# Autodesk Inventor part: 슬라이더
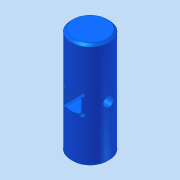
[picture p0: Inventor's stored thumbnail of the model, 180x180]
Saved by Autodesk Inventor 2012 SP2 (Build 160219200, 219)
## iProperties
Company: 한국ATC센터
Created: 2015-04
Part Number: 슬라이더
Document SubType Name: Modeling
Designer: KYOUNG IL JANG
Density: 7.85 g/cm^3
Material: 강
Author: KYOUNG IL JANG
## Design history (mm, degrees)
sketch "스케치1"
  geometry: C1 r 9 at (0, 0); 1 further point
  constraints: 1 centre point, 1 coincident
  dimensions: "d0" = 18 diameter of C1
extrude "돌출1" new body sketch "스케치1" stored distance "d1" = 50; taper "d2" = 0 deg
node "작업 평면1"
sketch "스케치3"
  geometry: L1 (4, 25)-(-4, 25); L2 (-4, 25)-(-4, -25); L3 (-4, -25)-(4, -25); L4 (4, -25)-(4, 25); 3 further points
  constraints: 8 end point, 2 midpoint, 2 parallel, 1 horizontal, 1 horizontal alignment, 1 perpendicular, 1 vertical alignment
  dimensions: "d5" = 8 distance of L1.start L1.end; "d6" = 50 distance of L1.end L2.end
extrude "돌출3" cut sketch "스케치3" stored distance "d7" = 8; taper "d8" = 0 deg
sketch "스케치4"
  geometry: 5 further points
hole "구멍1" sketch "스케치4" at (4, 4), (-4, 4), (-4, -4), (4, -4) diameter "d9" = 2; stored, may be unused: countersink angle "d13" = 90 deg, drill point angle "d15" = 118 deg; dims "d10" = 6, "d11" = 4, "d12" = 2, "d14" = 8
node "작업 평면2"
sketch "스케치5"
  geometry: 1 further point
hole "구멍2" sketch "스케치5" at (0, 0) diameter "d16" = 5; stored, may be unused: countersink angle "d20" = 90 deg, drill point angle "d22" = 118 deg; dims "d17" = 6, "d18" = 4, "d19" = 2, "d21" = 8
chamfer "모따기1" distance "d23" = 1; stored, may be unused: second distance "d24" = 2, angle "d25" = 45 deg
node "솔리드1"
mirror "대칭1"
